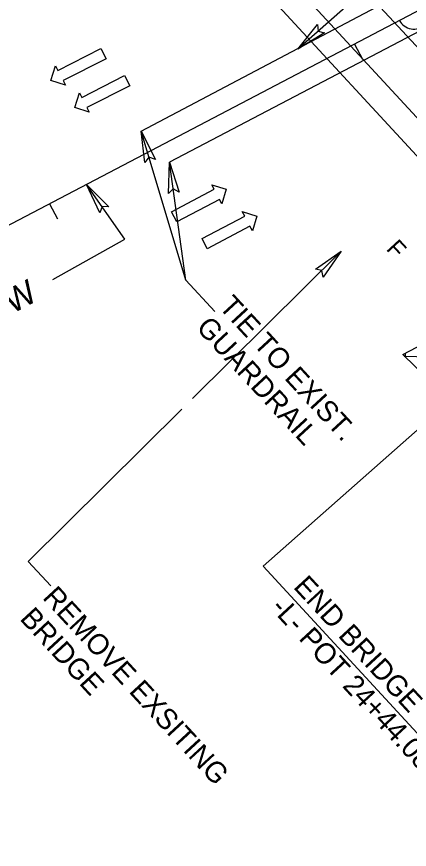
# Model space of a CAD drawing. Extents: x 1702862 to 1704514, y 793768 to 796215.
# Drawn here: x 1703456.2 to 1703570.3, y 794725.2 to 794966.9 of the extents above; entities that cross this region are included whole.
import ezdxf

# ---------------------------------------------------------------- set-up
doc = ezdxf.new("R2010")
doc.units = 0
for name, color, linetype in [('Exist Horizontal Alignment', 7, 'Continuous'), ('Exist Horizontal Alignment Direction Label', 7, 'Continuous'), ('Exist Horizontal Alignment Tick Small', 7, 'Continuous'), ('Prop Dimension', 7, 'Continuous'), ('Prop Dimension Text', 7, 'Continuous'), ('Prop DSN Text', 7, 'Continuous'), ('Prop EOT', 7, 'Continuous'), ('Prop Guardrail', 7, 'Continuous'), ('Prop Lane Arrow CELL', 7, 'Continuous'), ('Prop Lane Lines', 7, 'Continuous'), ('Prop Leader Line Medium', 7, 'Continuous'), ('Prop Rem of Exist Asph Pvmt', 7, 'Continuous'), ('Prop Roadway Bridge', 7, 'Continuous'), ('Prop SS Misc', 7, 'Continuous'), ('Prop Terminator CELL', 7, 'Continuous')]:
    doc.layers.add(name, color=color, linetype=linetype)

msp = doc.modelspace()

# ---------------------------------------------------------------- linework, layer by layer
at = {"layer": 'Exist Horizontal Alignment'}
msp.add_line((1703731.56, 795051.6), (1703391.21, 794873.6), dxfattribs=at)
at = {"layer": 'Exist Horizontal Alignment Direction Label'}
msp.add_lwpolyline([(1703466.74, 794890.55), (1703487.62, 794902.29), (1703476.47, 794918.19)], dxfattribs=at)
at = {"layer": 'Exist Horizontal Alignment Tick Small'}
for p, q in [((1703554.34, 794958.91), (1703556.65, 794954.48)), ((1703465.72, 794912.57), (1703468.04, 794908.14))]:
    msp.add_line(p, q, dxfattribs=at)
at = {"layer": 'Prop Dimension'}
msp.add_arc((1703571.59, 794967.94), 4.69, 207.6095, 312.7091, dxfattribs=at)
at = {"layer": 'Prop EOT'}
msp.add_line((1703418.98, 795103.79), (1703631.9, 794873.13), dxfattribs=at)
at = {"layer": 'Prop Guardrail'}
for p, q in [((1703492.38, 794933.6), (1703566.95, 794972.97)), ((1703575.44, 794963.77), (1703500.62, 794924.67))]:
    msp.add_line(p, q, dxfattribs=at)
at = {"layer": 'Prop Lane Arrow CELL'}
for p, q in [((1703468.2, 794951.23), (1703480.67, 794957.59)), ((1703480.67, 794957.59), (1703482.17, 794954.65)), ((1703482.17, 794954.65), (1703469.7, 794948.29)), ((1703466.17, 794948.28), (1703467.52, 794952.56)), ((1703467.52, 794952.56), (1703468.2, 794951.23)), ((1703475.1, 794943.39), (1703487.57, 794949.76)), ((1703487.57, 794949.76), (1703489.07, 794946.82)), ((1703470.39, 794946.95), (1703466.17, 794948.28)), ((1703469.7, 794948.29), (1703470.39, 794946.95)), ((1703489.07, 794946.82), (1703476.61, 794940.45)), ((1703473.07, 794940.45), (1703474.42, 794944.73)), ((1703474.42, 794944.73), (1703475.1, 794943.39)), ((1703477.29, 794939.12), (1703473.07, 794940.45)), ((1703476.61, 794940.45), (1703477.29, 794939.12)), ((1703513.59, 794916.75), (1703512.9, 794918.08)), ((1703512.9, 794918.08), (1703517.12, 794916.8)), ((1703501.19, 794910.26), (1703513.59, 794916.75)), ((1703517.12, 794916.8), (1703515.82, 794912.5)), ((1703515.12, 794913.83), (1703502.72, 794907.34)), ((1703515.82, 794912.5), (1703515.12, 794913.83)), ((1703502.72, 794907.34), (1703501.19, 794910.26)), ((1703522.46, 794908.94), (1703521.77, 794910.27)), ((1703521.77, 794910.27), (1703526, 794908.99)), ((1703510.06, 794902.45), (1703522.46, 794908.94)), ((1703526, 794908.99), (1703524.69, 794904.69)), ((1703524, 794906.02), (1703511.59, 794899.52)), ((1703524.69, 794904.69), (1703524, 794906.02)), ((1703511.59, 794899.52), (1703510.06, 794902.45))]:
    msp.add_line(p, q, dxfattribs=at)
at = {"layer": 'Prop Lane Lines'}
msp.add_line((1703549.28, 794983.27), (1703583.2, 794946.52), dxfattribs=at)
at = {"layer": 'Prop Leader Line Medium'}
for p, q in [((1703695.56, 795097.27), (1703537.91, 794957.38)), ((1703505.35, 794890.4), (1703492.38, 794933.6)), ((1703505.35, 794890.4), (1703500.62, 794924.67)), ((1703633.55, 794900.82), (1703527.8, 794807.39)), ((1703507.34, 794856.01), (1703550.53, 794898.76)), ((1703505.35, 794890.4), (1703513.76, 794881.29)), ((1703459.59, 794808.73), (1703504.23, 794852.93)), ((1703466.09, 794801.68), (1703459.59, 794808.73)), ((1703527.8, 794807.39), (1703603.65, 794725.22))]:
    msp.add_line(p, q, dxfattribs=at)
at = {"layer": 'Prop Rem of Exist Asph Pvmt'}
for p, q in [((1703569.12, 794869.19), (1703569.08, 794868.13)), ((1703568.82, 794868.38), (1703597.22, 794867.25))]:
    msp.add_line(p, q, dxfattribs=at)
for points in [[(1703568.38, 794868.8), (1703590.81, 794880.55)], [(1703579.1, 794858.48), (1703568.38, 794868.8)]]:
    msp.add_lwpolyline(points, dxfattribs=at)
at = {"layer": 'Prop Roadway Bridge'}
msp.add_line((1703486.23, 795019.87), (1703608.29, 794887.64), dxfattribs=at)
at = {"layer": 'Prop Terminator CELL'}
for points in [[(1703545.67, 794962.2), (1703537.91, 794957.38), (1703543.61, 794964.59), (1703543.82, 794962.63)], [(1703493.48, 794924.54), (1703492.38, 794933.6), (1703496.51, 794925.4), (1703494.65, 794926.04)], [(1703500.32, 794915.54), (1703500.62, 794924.67), (1703503.45, 794915.92), (1703501.7, 794916.85)], [(1703480.37, 794909.93), (1703476.47, 794918.19), (1703482.97, 794911.7), (1703481, 794911.72)], [(1703543.04, 794893.53), (1703550.53, 794898.76), (1703545.22, 794891.26), (1703544.92, 794893.21)]]:
    msp.add_lwpolyline(points, close=True, dxfattribs=at)

# ---------------------------------------------------------------- texts
at = {"layer": 'Exist Horizontal Alignment Direction Label'}
msp.add_text('S 62%%d 23\' 25.7" W', height=7, rotation=27.6095, dxfattribs=at).set_placement((1703397.64, 794850.61))
at = {"layer": 'Prop Dimension Text'}
for s, p in [('TIE TO EXIST.', (1703514.72, 794882.5)), ('GUARDRAIL', (1703508.11, 794876.4)), ('REMOVE EXSITING', (1703463.48, 794798.1)), ('BRIDGE', (1703456.87, 794791.99))]:
    msp.add_text(s, height=6, rotation=312.7091, dxfattribs=at).set_placement(p)
at = {"layer": 'Prop DSN Text'}
for s, p in [('END BRIDGE', (1703536.36, 794801.21)), ('-L- POT 24+44.08 +/-', (1703529.75, 794795.11))]:
    msp.add_text(s, height=6, rotation=312.7091, dxfattribs=at).set_placement(p)
at = {"layer": 'Prop SS Misc'}
msp.add_text('F', height=5, rotation=312.7091, dxfattribs=at).set_placement((1703563.36, 794899.3))

doc.saveas('drawing.dxf')
